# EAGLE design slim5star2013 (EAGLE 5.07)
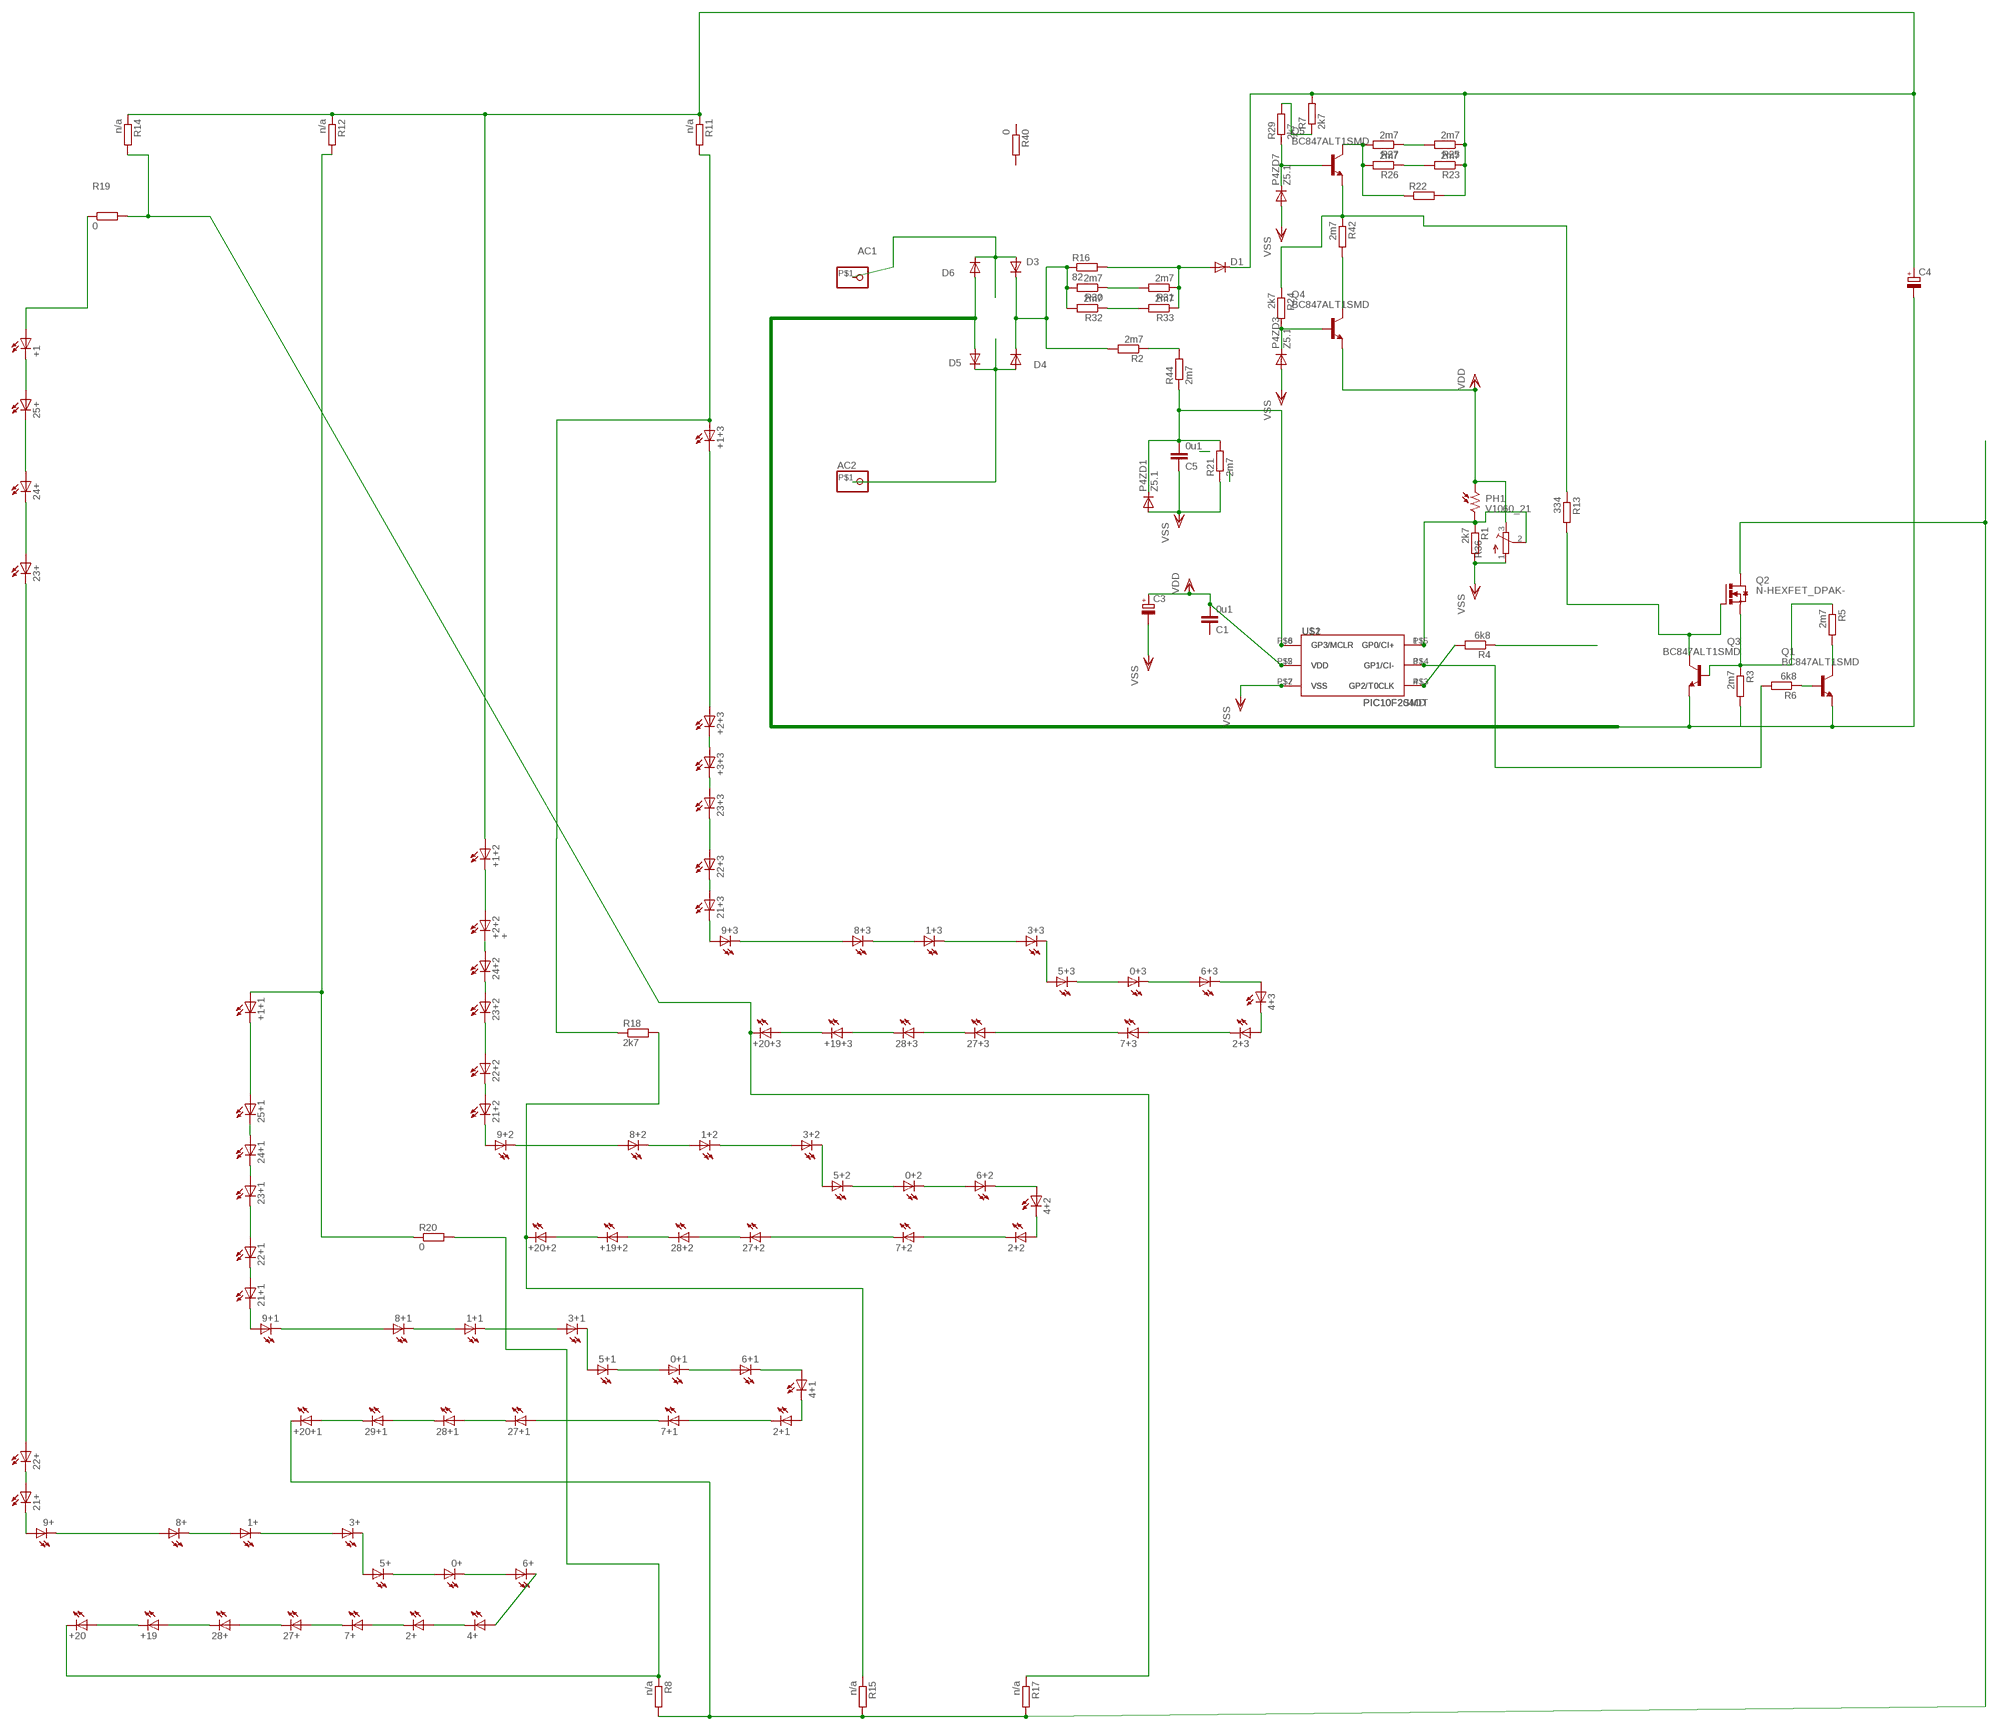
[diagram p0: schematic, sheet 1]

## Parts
0+  LED1210  [1210]
0+1  LED1210  [1210]
0+2  LED1210  [1210]
0+3  LED1210  [1210]
1+  LED1210  [1210]
1+1  LED1210  [1210]
1+2  LED1210  [1210]
1+3  LED1210  [1210]
2+  LED1210  [1210]
2+1  LED1210  [1210]
2+2  LED1210  [1210]
2+3  LED1210  [1210]
3+  LED1210  [1210]
3+1  LED1210  [1210]
3+2  LED1210  [1210]
3+3  LED1210  [1210]
4+  LED1210  [1210]
4+1  LED1210  [1210]
4+2  LED1210  [1210]
4+3  LED1210  [1210]
5+  LED1210  [1210]
5+1  LED1210  [1210]
5+2  LED1210  [1210]
5+3  LED1210  [1210]
6+  LED1210  [1210]
6+1  LED1210  [1210]
6+2  LED1210  [1210]
6+3  LED1210  [1210]
7+  LED1210  [1210]
7+1  LED1210  [1210]
7+2  LED1210  [1210]
7+3  LED1210  [1210]
8+  LED1210  [1210]
8+1  LED1210  [1210]
8+2  LED1210  [1210]
8+3  LED1210  [1210]
9+  LED1210  [1210]
9+1  LED1210  [1210]
9+2  LED1210  [1210]
9+3  LED1210  [1210]
21+  LED1210  [1210]
21+1  LED1210  [1210]
21+2  LED1210  [1210]
21+3  LED1210  [1210]
22+  LED1210  [1210]
22+1  LED1210  [1210]
22+2  LED1210  [1210]
22+3  LED1210  [1210]
23+  LED1210  [1210]
23+1  LED1210  [1210]
23+2  LED1210  [1210]
23+3  LED1210  [1210]
24+  LED1210  [1210]
24+1  LED1210  [1210]
24+2  LED1210  [1210]
25+  LED1210  [1210]
25+1  LED1210  [1210]
27+  LED1210  [1210]
27+1  LED1210  [1210]
27+2  LED1210  [1210]
27+3  LED1210  [1210]
28+  LED1210  [1210]
28+1  LED1210  [1210]
28+2  LED1210  [1210]
28+3  LED1210  [1210]
29+1  LED1210  [1210]
+1  LED1210  [1210]
+1+1  LED1210  [1210]
+1+2  LED1210  [1210]
+1+3  LED1210  [1210]
+2+2  +  LED1210  [1210]
+2+3  LED1210  [1210]
+3+3  LED1210  [1210]
+19  LED1210  [1210]
+19+2  LED1210  [1210]
+19+3  LED1210  [1210]
+20  LED1210  [1210]
+20+1  LED1210  [1210]
+20+2  LED1210  [1210]
+20+3  LED1210  [1210]
AC1  PINHD-1X1SMD  [SMD1X1]
AC2  PINHD-1X1SMD  [SMD1X1]
C1  0u1  C-EUC1206  [C1206]
C3  CPOL-EUE  [PANASONIC_E]
C4  CPOL-EUSANYO_SMD_F12  [SANYO-OSCON_SMD_F12]
C5  0u1  C-EUC1206  [C1206]
D1  DIODE-MINIMELF  [MINIMELF]
D3  DIODE-SOD80C  [SOD80C]
D4  DIODE-SOD80C  [SOD80C]
D5  DIODE-SOD80C  [SOD80C]
D6  DIODE-SOD80C  [SOD80C]
P4ZD1  Z5.1  DIODE-MINIMELF  [MINIMELF]
P4ZD3  Z5.1  DIODE-MINIMELF  [MINIMELF]
P4ZD7  Z5.1  DIODE-MINIMELF  [MINIMELF]
PH1  V1060_21  [TO-5_V10]
Q1  BC847ALT1SMD  [SOT23]
Q2  N-HEXFET_DPAK-  [TO252]
Q3  BC847ALT1SMD  [SOT23]
Q4  BC847ALT1SMD  [SOT23]
Q5  BC847ALT1SMD  [SOT23]
R1  2k7  R-EU_R1206  [R1206]
R2  2m7  R-EU_R2010  [R2010]
R3  2m7  R-EU_R1210  [R1210]
R4  6k8  R-EU_R1206  [R1206]
R5  2m7  R-EU_R1210  [R1210]
R6  6k8  R-EU_R1206  [R1206]
R7  2k7  R-EU_R1206  [R1206]
R8  n/a  R-EU_R0402  [R0402]
R11  n/a  R-EU_R0402  [R0402]
R12  n/a  R-EU_R0402  [R0402]
R13  334  R-EU_R1206  [R1206]
R14  n/a  R-EU_R0402  [R0402]
R15  n/a  R-EU_R0402  [R0402]
R16  82  R-EU_SMD15  [SMDCARB15]
R17  n/a  R-EU_R0402  [R0402]
R18  2k7  R-EU_R0402  [R0402]
R19  0  R-EU_R0402  [R0402]
R20  0  R-EU_R0402  [R0402]
R21  2m7  R-EU_R1206  [R1206]
R22  R-EU_SMD15  [SMDCARB15]
R23  2m7  R-EU_R1210  [R1210]
R24  2k7  R-EU_R1206  [R1206]
R25  2m7  R-EU_R1210  [R1210]
R26  2m7  R-EU_R1210  [R1210]
R27  2m7  R-EU_R1210  [R1210]
R29  2k7  R-EU_R1206  [R1206]
R30  2m7  R-EU_R1210  [R1210]
R31  2m7  R-EU_R1210  [R1210]
R32  2m7  R-EU_R1210  [R1210]
R33  2m7  R-EU_R1210  [R1210]
R36  TRIM_EU-SM-42/43A  [SM-42/43A]
R40  0  R-EU_R2010  [R2010]
R42  2m7  R-EU_R2010  [R2010]
R44  2m7  R-EU_R2010  [R2010]
U$1  PIC10F2SMD  [DIL8SMD]
U$2  PIC10F204OT  [SOT23-6]

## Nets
AC1: Q5.2(E) R13.1 R24.1 R42.1
AC2: AC2.P$1 D4.A D5.C
BATT-: C4.- D5.A D6.A Q1.2(E) Q3.2(E) R3.2
D+: +1+2.P$1(A) C4.+ D1.C R7.2 R11.1 R12.1 R14.1 R22.P$2 R23.1 R25.1
MINUS: +20+1.P$2(C) Q2.3(D) R8.2 R15.2 R17.2
N$1: +1+3.P$1(A) R11.2 R18.1
N$2: +1+1.P$1(A) R12.2 R20.1
N$4: +1.P$1(A) R19.1
N$5: Q4.3(C) R42.2
N$6: 8+.P$1(A) 9+.P$2(C)
N$7: +19.P$2(C) +20.P$1(A)
N$8: 28+.P$2(C) +19.P$1(A)
N$9: 27+.P$2(C) 28+.P$1(A)
N$10: 29+1.P$2(C) +20+1.P$1(A)
N$11: 28+1.P$2(C) 29+1.P$1(A)
N$12: 2+.P$2(C) 7+.P$1(A)
N$13: 7+.P$2(C) 27+.P$1(A)
N$14: 2+.P$1(A) 4+.P$2(C)
N$15: 4+.P$1(A) 6+.P$2(C)
N$16: 0+.P$2(C) 6+.P$1(A)
N$17: 0+.P$1(A) 5+.P$2(C)
N$18: 3+.P$2(C) 5+.P$1(A)
N$19: 1+.P$2(C) 3+.P$1(A)
N$20: 1+.P$1(A) 8+.P$2(C)
N$21: 27+1.P$2(C) 28+1.P$1(A)
N$22: 2+1.P$1(A) 4+1.P$2(C)
N$23: 9+.P$1(A) 21+.P$2(C)
N$24: 21+.P$1(A) 22+.P$2(C)
N$25: 22+.P$1(A) 23+.P$2(C)
N$26: 24+.P$1(A) 25+.P$2(C)
N$27: 25+.P$1(A) +1.P$2(C)
N$28: 23+.P$1(A) 24+.P$2(C)
N$29: 4+1.P$1(A) 6+1.P$2(C)
N$30: 0+1.P$2(C) 6+1.P$1(A)
N$31: 0+1.P$1(A) 5+1.P$2(C)
N$32: 3+1.P$2(C) 5+1.P$1(A)
N$33: 1+1.P$2(C) 3+1.P$1(A)
N$34: 1+1.P$1(A) 8+1.P$2(C)
N$35: 9+1.P$1(A) 21+1.P$2(C)
N$36: 21+1.P$1(A) 22+1.P$2(C)
N$37: 22+1.P$1(A) 23+1.P$2(C)
N$38: 25+1.P$1(A) +1+1.P$2(C)
N$39: 24+1.P$1(A) 25+1.P$2(C)
N$40: 23+1.P$1(A) 24+1.P$2(C)
N$41: 2+1.P$2(C) 7+1.P$1(A)
N$42: 7+1.P$2(C) 27+1.P$1(A)
N$43: 8+1.P$1(A) 9+1.P$2(C)
N$45: +20+3.P$2(C) R14.2 R17.1 R19.2
N$46: +19+2.P$2(C) +20+2.P$1(A)
N$47: 28+2.P$2(C) +19+2.P$1(A)
N$48: 27+2.P$2(C) 28+2.P$1(A)
N$49: 2+2.P$1(A) 4+2.P$2(C)
N$50: 4+2.P$1(A) 6+2.P$2(C)
N$51: 0+2.P$2(C) 6+2.P$1(A)
N$52: 0+2.P$1(A) 5+2.P$2(C)
N$53: 3+2.P$2(C) 5+2.P$1(A)
N$54: 1+2.P$2(C) 3+2.P$1(A)
N$55: 1+2.P$1(A) 8+2.P$2(C)
N$56: 9+2.P$1(A) 21+2.P$2(C)
N$57: 21+2.P$1(A) 22+2.P$2(C)
N$58: 22+2.P$1(A) 23+2.P$2(C)
N$59: +1+2.P$2(C) +2+2.P$1(A)
N$60: 24+2.P$1(A) +2+2.P$2(C)
N$61: 23+2.P$1(A) 24+2.P$2(C)
N$62: 2+2.P$2(C) 7+2.P$1(A)
N$63: 7+2.P$2(C) 27+2.P$1(A)
N$64: 8+2.P$1(A) 9+2.P$2(C)
N$65: +20+2.P$2(C) R15.1 R18.2
N$66: +20.P$2(C) R8.1 R20.2
N$67: +19+3.P$2(C) +20+3.P$1(A)
N$68: 28+3.P$2(C) +19+3.P$1(A)
N$69: 27+3.P$2(C) 28+3.P$1(A)
N$70: 2+3.P$1(A) 4+3.P$2(C)
N$71: 4+3.P$1(A) 6+3.P$2(C)
N$72: 0+3.P$2(C) 6+3.P$1(A)
N$73: 0+3.P$1(A) 5+3.P$2(C)
N$74: 3+3.P$2(C) 5+3.P$1(A)
N$75: 1+3.P$2(C) 3+3.P$1(A)
N$76: 1+3.P$1(A) 8+3.P$2(C)
N$77: 9+3.P$1(A) 21+3.P$2(C)
N$78: 21+3.P$1(A) 22+3.P$2(C)
N$79: 22+3.P$1(A) 23+3.P$2(C)
N$80: +1+3.P$2(C) +2+3.P$1(A)
N$81: +2+3.P$2(C) +3+3.P$1(A)
N$82: 23+3.P$1(A) +3+3.P$2(C)
N$83: 2+3.P$2(C) 7+3.P$1(A)
N$84: 7+3.P$2(C) 27+3.P$1(A)
N$85: 8+3.P$1(A) 9+3.P$2(C)
N$86: D1.A R16.P$2 R31.1 R33.1
N$88: PH1.2 R1.1 R36.2(S) U$1.P$5(GP0/CI+) U$2.1(GP0/CI+)
N$91: D3.C D4.C R2.2 R16.P$1 R30.2 R32.2
N$92: Q5.3(C) R22.P$1 R26.2 R27.2
N$93: AC1.P$1 D3.A D6.C
N$94: Q2.1(G) Q3.3(C) R13.2
N$95: R4.2 U$1.P$3(GP2/T0CLK) U$2.4(GP2/T0CLK)
N$96: C5.2 P4ZD1.C R21.2 R44.1 U$1.P$8(GP3/MCLR) U$2.6(GP3/MCLR)
N$97: R2.1 R44.2
N$98: Q1.1(B) R6.1
N$99: R23.2 R26.1
N$100: R25.2 R27.1
N$101: Q1.3(C) R5.2
N$102: R6.2 U$1.P$4(GP1/CI-) U$2.3(GP1/CI-)
N$103: P4ZD3.C Q4.1(B) R24.2
N$104: P4ZD7.C Q5.1(B) R29.1
N$105: Q2.2(S) Q3.1(B) R3.1 R5.1
N$106: R7.1 R29.2
N$107: R30.1 R31.2
N$108: R32.1 R33.2
PIR: R4.1
VDD: C1.2 C3.+ PH1.1 Q4.2(E) R36.3(E) U$1.P$2(VDD) U$2.5(VDD)
VSS: C3.- C5.1 P4ZD1.A P4ZD3.A P4ZD7.A R1.2 R21.1 R36.1(A) U$1.P$7(VSS) U$2.2(VSS)
Unconnected: C1.1 R40.1 R40.2

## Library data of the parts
0+ 0+1-0+3 1+ 1+1-1+3 2+ 2+1-2+3 3+ 3+1-3+3 4+ 4+1-4+3 5+ 5+1-5+3 6+ 6+1-6+3 7+ 7+1-7+3 8+ 8+1-8+3 9+ 9+1-9+3 21+ 21+1-21+3 22+ 22+1-22+3 23+ 23+1-23+3 24+ 24+1 24+2 25+ 25+1 27+ 27+1-27+3 28+ 28+1-28+3 29+1 +1 +1+1-+1+3 +2+2 +2+3 +3+3 +19 +19+2 +19+3 +20 +20+1-+20+3 = led(2):LED: LED
AC1 AC2 = pinhead:PINHD-1X1: PIN HEADER
C1 C5 = rcl:C-EU: CAPACITOR, European symbol
C3 C4 = rcl-2:CPOL-EU: POLARIZED CAPACITOR, European symbol
D1 D3-D6 P4ZD1 P4ZD3 P4ZD7 = diode:DIODE-: DIODE
PH1 = photo-elements:?1060*: Sensor Street Light control
Q1 Q3-Q5 = transistor-npn:BC847*: NPN Transistor
Q2 = transistor-power:N-HEXFET_?-*: HEXFET® Power MOSFET
R1-R8 R11-R15 R17-R21 R23-R27 R29-R33 R40 R42 R44 = rcl-2:R-EU_: RESISTOR, European symbol
R16 R22 = rcl:R-EU_: RESISTOR, European symbol
R36 = pot:TRIM_EU-: POTENTIOMETER
U$1 U$2 = microchip-5:PIC10F2*: uPC nW 0,25/0,5k Program Flash memory Comparator

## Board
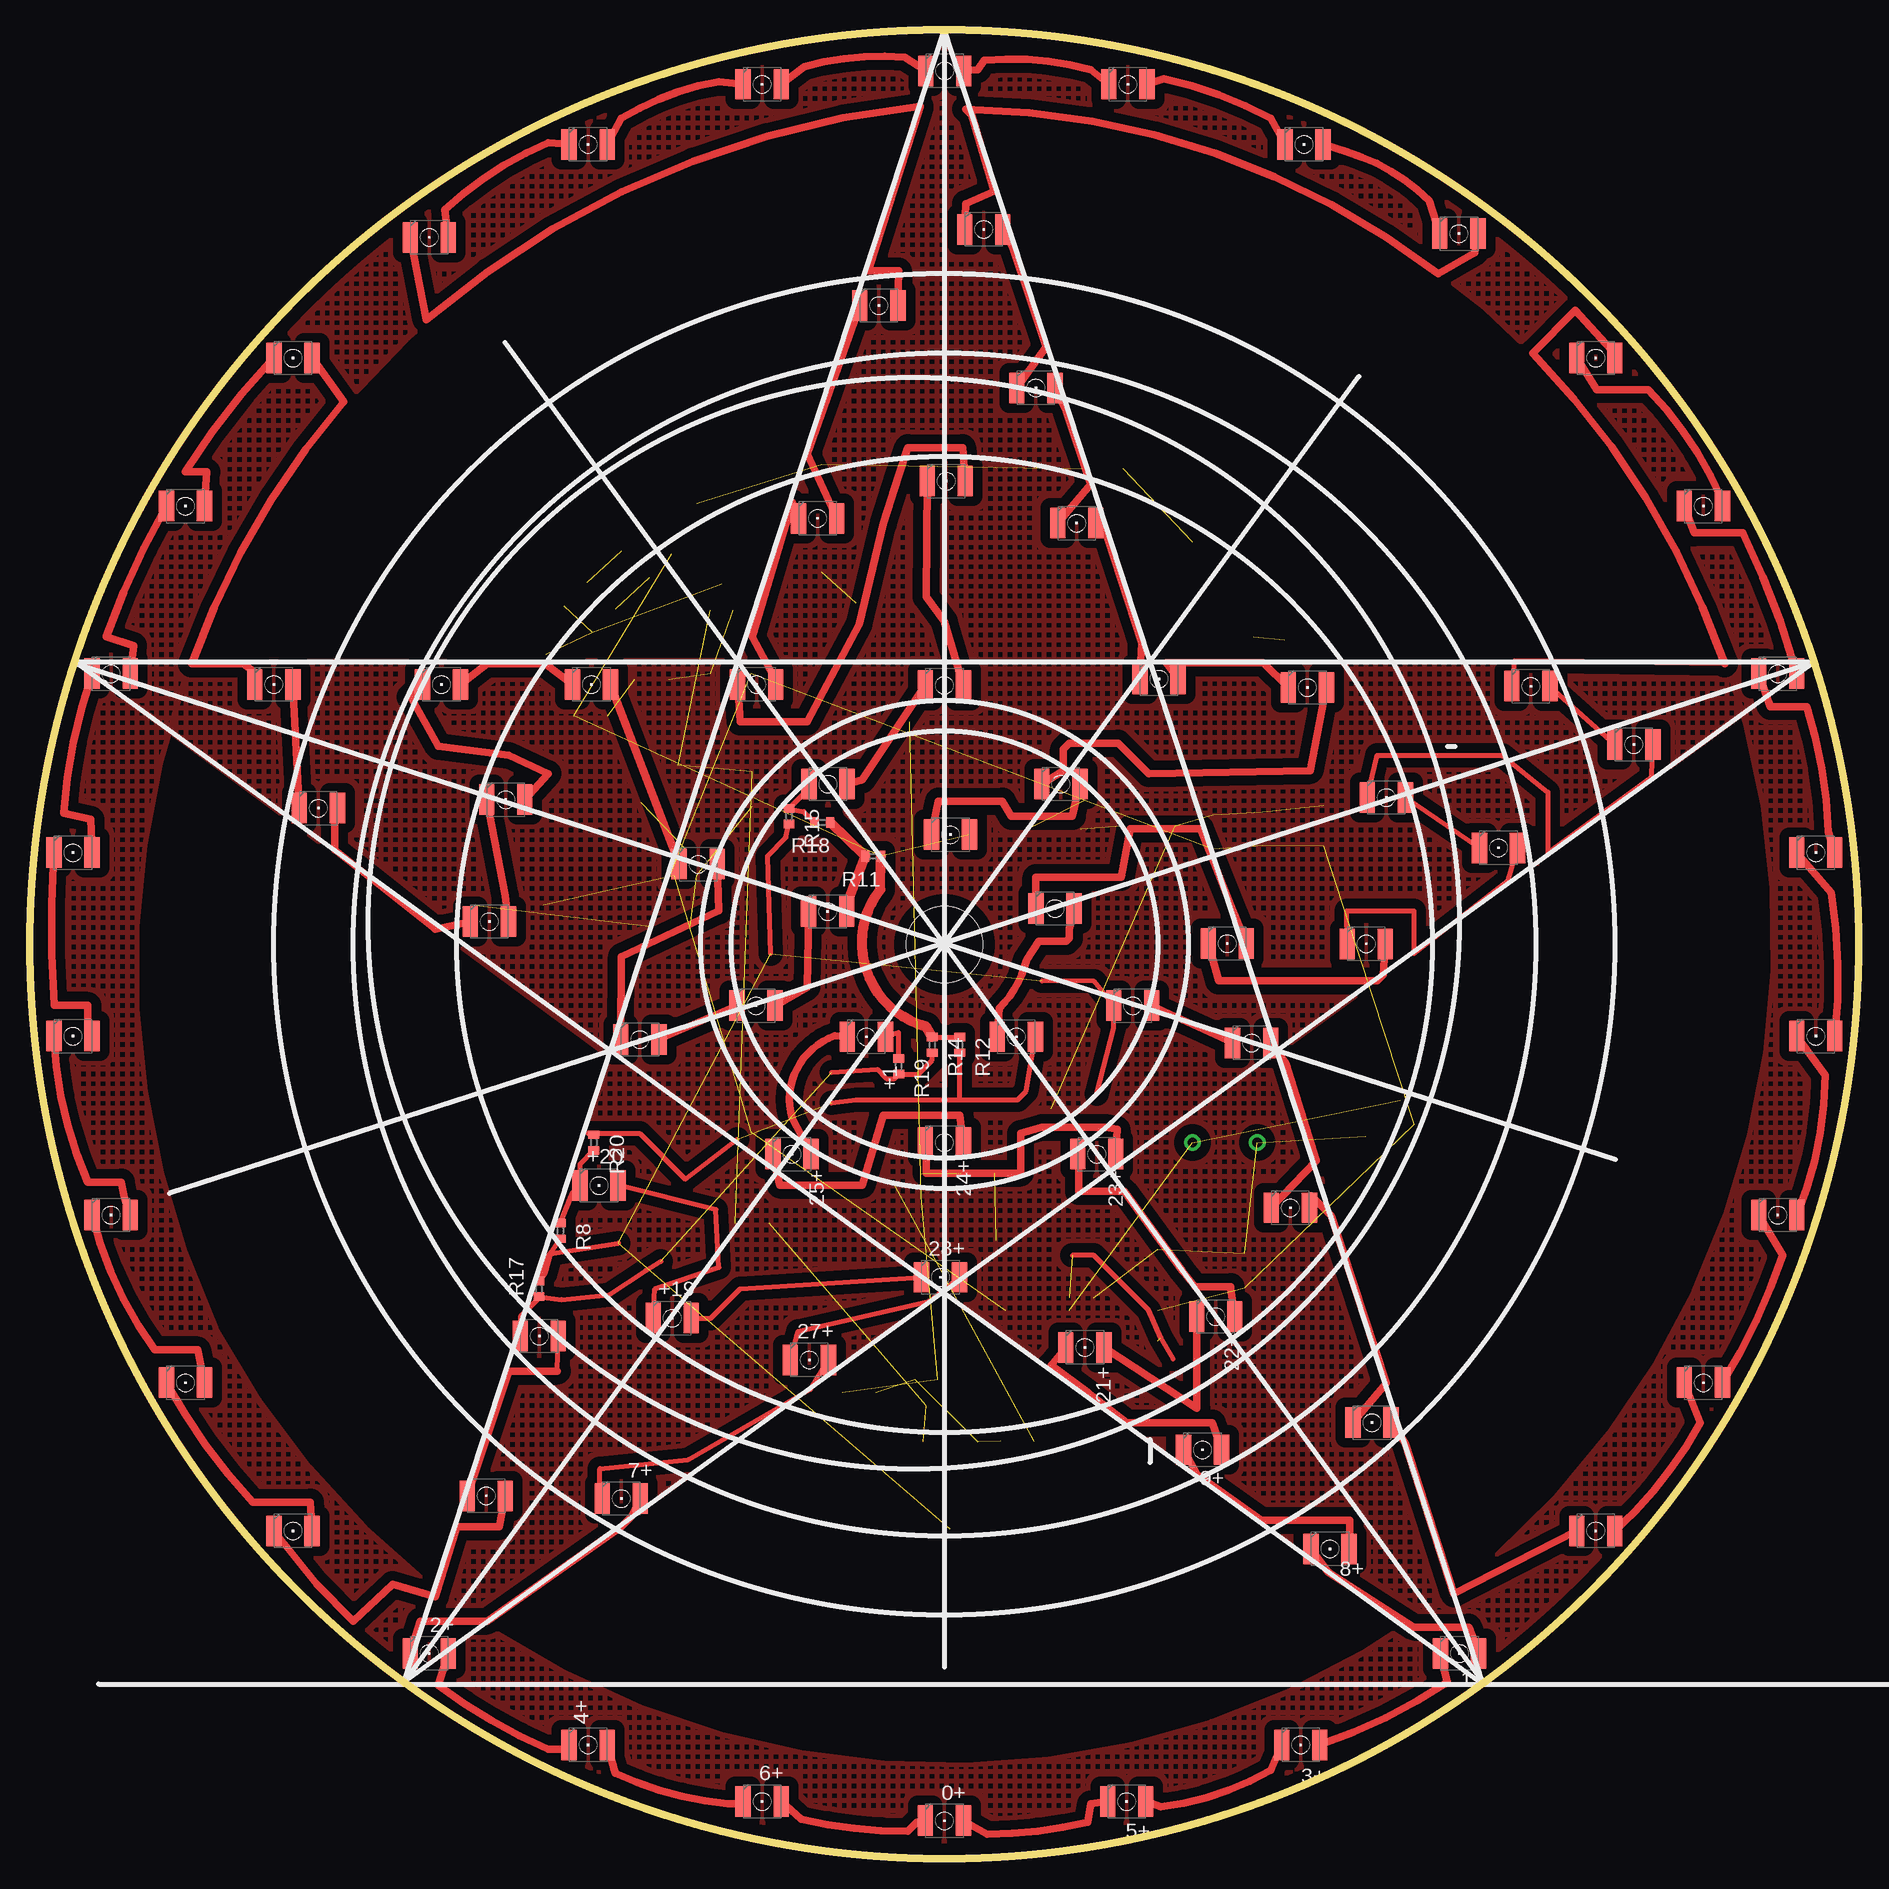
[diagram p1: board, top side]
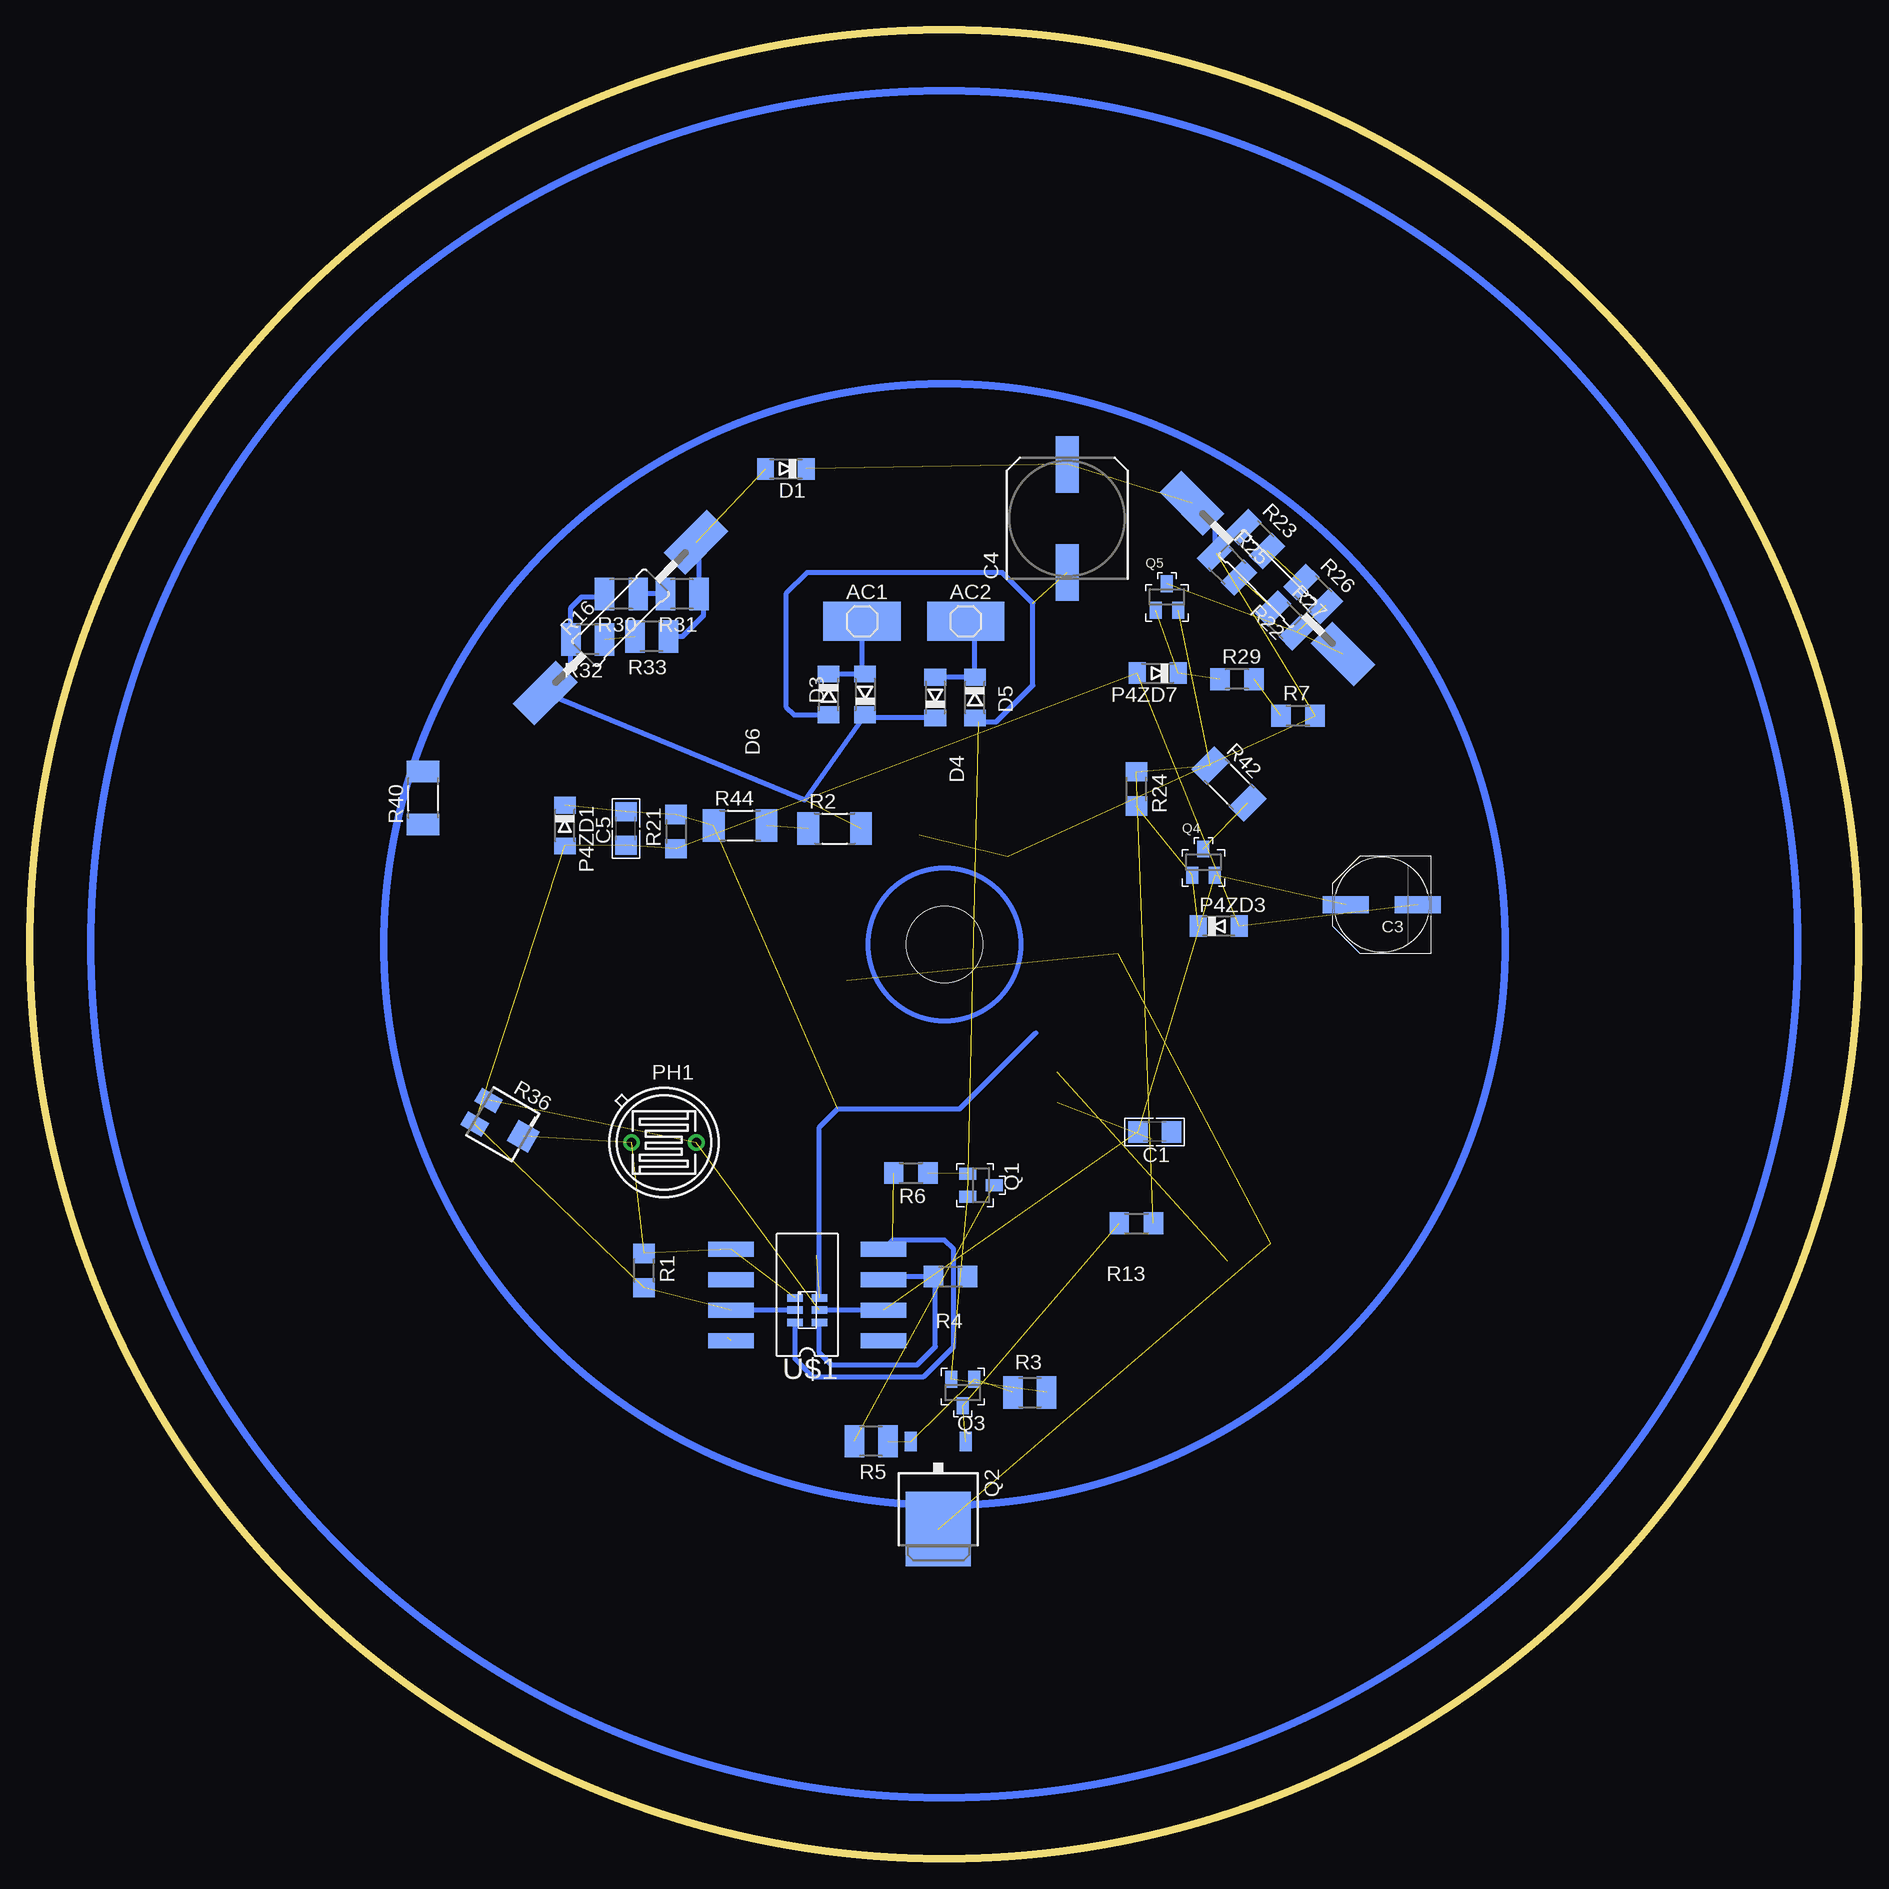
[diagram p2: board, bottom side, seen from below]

Size 152.4 x 152.4 mm. Coordinates in mm from the lower left corner, seen from the top.
Outline: circle at 76.2,76.2 radius 76.2
Copper layers (1*16): Top 0.035mm / dielectric 1.5mm / Bottom 0.035mm
Design rules "default": minimum track width 10mil, minimum drill 24mil, track to track 8mil, track to pad 8mil, pad to pad 8mil, via to via 8mil, smd to smd 8mil, copper to edge 40mil, drill to drill 8mil, minimum pad ring 10mil, minimum via ring 8mil, stop-mask expansion 4mil, vias tented up to drill 0mil, thermal gap 10mil
Holes 6.35 mm at 76.2,76.2

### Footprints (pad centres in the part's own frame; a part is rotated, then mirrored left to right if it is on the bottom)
1210 = smd 1.27 x 2.54: P$1 1.587,0; P$2 -1.587,0
SMD1X1 = smd 6.452 x 3.251: P$1 0,0
C1206 = smd 1.6 x 1.8: 1 -1.4,0; 2 1.4,0
PANASONIC_E = smd 3.8 x 1.4: + 3,0; - -3,0
SANYO-OSCON_SMD_F12 = smd 4.7 x 1.9: + 4.5,0; - -4.5,0
MINIMELF = smd 1.4 x 1.8: A 1.7,0; C -1.7,0
SOD80C = smd 1.4 x 1.8: A 1.7,0; C -1.7,0
TO-5_V10 = drill 0.8 pad 1.4 round: 1 -2.7,0; 2 2.7,0
SOT23 = smd 1 x 1.4: 1 -0.95,-1.1; 2 0.95,-1.1; 3 0,1.1
TO252 = smd 1 x 1.6: 1 -2.28,-3.53; 2 2.28,-3.53 | smd 5.4 x 6.2: 3 0,3.77
R1206 = smd 1.6 x 1.803: 1 -1.422,0; 2 1.422,0
R2010 = smd 1.8 x 2.7: 1 -2.2,0; 2 2.2,0
R1210 = smd 1.6 x 2.7: 1 -1.4,0; 2 1.4,0
R0402 = smd 0.7 x 0.9: 1 -0.65,0; 2 0.65,0
SMDCARB15 = smd 5.08 x 2.54: P$1 -8.89,0; P$2 8.89,0
SM-42/43A = smd 2 x 1.3: 1 2,1.15; 3 2,-1.15 | smd 2 x 2: 2 -2,0
DIL8SMD = smd 1.27 x 3.81: P$1 -3.81,-6.35; P$2 -1.27,-6.35; P$3 1.27,-6.35; P$4 3.81,-6.35; P$5 3.81,6.35; P$6 1.27,6.35; P$7 -1.27,6.35; P$8 -3.81,6.35
SOT23-6 = smd 0.635 x 1.27: 1 -1.016,-1.016; 2 0,-1.016; 3 1.016,-1.016; 4 1.016,1.016; 5 0,1.016; 6 -1.016,1.016

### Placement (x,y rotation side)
0+  76.2,3.17 0 top
0+1  148.82,83.85 0 top
0+2  61.01,147.88 0 top
0+3  12.95,112.73 0 top
1+  119.13,17.12 0 top
1+1  130.48,125.07 0 top
1+2  106.17,142.88 0 top
1+3  24.03,87.55 0 top
2+  33.27,17.12 0 top
2+1  139.45,39.67 0 top
2+2  70.74,129.44 0 top
2+3  3.58,68.55 0 top
3+  105.89,9.5 0 top
3+1  139.45,112.73 0 top
3+2  91.49,147.88 0 top
3+3  20.32,97.87 0 top
4+  46.51,9.5 0 top
4+1  145.64,53.64 0 top
4+2  33.27,135.13 0 top
4+3  3.58,83.85 0 top
5+  91.39,4.78 0 top
5+1  145.64,98.76 0 top
5+2  76.23,149 0 top
5+3  21.92,125.07 0 top
6+  61.01,4.78 0 top
6+1  148.82,68.55 0 top
6+2  46.51,142.88 0 top
6+3  6.76,98.76 0 top
7+  49.28,30.02 0 top
7+1  130.48,27.33 0 top
7+2  65.63,111.71 0 top
7+3  6.76,53.64 0 top
8+  108.33,25.83 0 top
8+1  125.07,97.71 0 top
8+2  119.08,135.43 0 top
8+3  38.28,78.11 0 top
9+  97.71,34.09 0 top
9+1  133.65,92.86 0 top
9+2  79.48,135.79 0 top
9+3  39.65,88.27 0 top
21+  87.91,42.62 0 top
21+1  113.03,88.44 0 top
21+2  83.82,122.58 0 top
21+3  34.29,97.87 0 top
22+  98.81,45.19 0 top
22+1  122.38,84.25 0 top
22+2  87.22,111.3 0 top
22+3  46.79,97.87 0 top
23+  88.9,58.72 0 top
23+1  111.35,76.25 0 top
23+2  94.08,98.32 0 top
23+3  55.68,82.88 0 top
24+  76.2,59.69 0 top
24+1  99.77,76.28 0 top
24+2  106.45,97.61 0 top
25+  63.5,58.72 0 top
25+1  85.42,79.2 0 top
27+  64.95,41.58 0 top
27+1  111.84,36.35 0 top
27+2  60.55,97.87 0 top
27+3  12.95,39.67 0 top
28+  75.87,48.46 0 top
28+1  105.03,54.25 0 top
28+2  76.35,114.81 0 top
28+3  21.92,27.33 0 top
29+1  101.8,68 0 top
+1  69.7,68.5 0 top
+1+1  82.19,68.5 0 top
+1+2  76.71,85.34 0 top
+1+3  66.47,78.94 0 top
+2+2  85.9,89.56 0 top
+2+3  60.5,71.09 0 top
+3+3  50.83,68.28 0 top
+19  53.52,45.06 0 top
+19+2  76.2,97.79 0 top
+19+3  38.02,30.25 0 top
+20  47.42,56.11 0 top
+20+1  91.9,71.09 0 top
+20+2  66.5,89.56 0 top
+20+3  42.44,43.56 0 top
AC1  83.06,103.12 0 bottom
AC2  74.42,103.12 0 bottom
C1  58.67,60.58 180 bottom
C3  39.75,79.5 180 bottom
C4  65.97,111.7 90 bottom
C5  102.74,85.85 90 bottom
D1  89.41,115.82 180 bottom
D3  82.8,97.03 90 bottom
D4  76.96,96.77 90 bottom
D5  73.66,96.77 270 bottom
D6  85.85,97.03 270 bottom
P4ZD1  107.82,86.11 270 bottom
P4ZD3  53.34,77.72 0 bottom
P4ZD7  58.42,98.81 180 bottom
PH1  99.57,59.69 180 bottom
Q1  73.15,56.13 270 bottom
Q2  76.71,31.24 180 bottom
Q3  74.68,38.86 180 bottom
Q4  54.61,83.06 0 bottom
Q5  57.66,105.16 0 bottom
R1  101.22,49.02 270 bottom
R2  85.34,85.85 0 bottom
R3  69.09,38.86 0 bottom
R4  75.69,48.51 180 bottom
R5  82.3,34.8 180 bottom
R6  78.99,57.15 180 bottom
R7  46.74,95.25 0 bottom
R8  44.2,52.32 270 top
R11  70.26,83.55 180 top
R12  77.47,67.82 270 top
R13  60.2,52.96 180 bottom
R14  75.18,67.82 270 top
R15  63.25,86.87 270 top
R16  103.18,103.43 45 bottom
R17  42.42,47.5 90 top
R18  66.04,86.36 180 top
R19  72.39,66.04 270 top
R20  46.99,59.69 270 top
R21  98.55,85.6 90 bottom
R22  49.28,106.68 135 bottom
R23  50.29,109.98 315 bottom
R24  60.2,89.15 270 bottom
R25  52.65,107.77 315 bottom
R26  45.47,105.41 315 bottom
R27  47.83,103.2 315 bottom
R29  51.82,98.3 0 bottom
R30  103.12,105.41 180 bottom
R31  98.04,105.41 180 bottom
R32  105.92,101.6 180 bottom
R33  100.58,101.85 180 bottom
R36  113.03,61.21 150 bottom
R40  119.63,88.39 90 bottom
R42  52.47,89.56 315 bottom
R44  93.22,86.11 0 bottom
U$1  87.63,46.99 90 bottom
U$2  87.63,45.72 270 bottom

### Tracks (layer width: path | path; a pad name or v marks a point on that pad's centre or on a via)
AC1  (3 unrouted)
AC2
  Bottom 0.406: AC2.P$1 73.66,103.12 D5.C D4.A
BATT-  (4 unrouted)
  Bottom 0.406: D6.A 88.72,95.33 89.41,96.01 89.41,105.41 87.63,107.19 71.37,107.19 68.83,104.65 68.83,97.79 71.88,94.74 73.33,94.74 D5.A
D+  (5 unrouted)
  Top 0.406: R14.1 R12.1
  Top 0.813: R14.1 74.68,69.34 arc-113 70.87,80.77 R11.1
  Bottom 0.406: R23.1 53.49,108.76 R25.1 53.64,111.05 R22.P$2
MINUS  (3 unrouted)
  Top 0.406: R15.2 62.99,85.09 61.47,83.57 61.72,75.44 | 49.02,51.31 43.32,50.43 R17.2 42.93,48.77 43.43,50.55 R8.2 | 84.33,73.15 88.67,73.13 +20+1.P$2 90.31,69.23 88.9,63.75
N$1
  Top 0.813: R18.1 R11.2 68.07,79.5 +1+3.P$1
N$2  (1 unrouted)
  Top 0.406: +1+1.P$1 83.02,63.97 82.3,63.25 77.47,63.25 | 66.8,62.99 68.83,63.25 77.47,63.25 | 58.93,59.94 54.61,56.64 50.8,60.45 46.88,60.45 | 46.88,60.45 46.48,60.45 | R20.1 46.88,60.45 | 77.47,63.25 R12.2
N$3
  pour Top (isolate 0.813, hatched): 48.31,66.78 31.24,14.66 76.33,47.45 120.95,14.66 104.27,67.36 148.74,99.77 93.29,99.72 76.2,152.4 59.18,99.87 3.76,99.75
N$4
  Top 0.406: R19.1 72.39,68.85 +1.P$1
N$5  (1 unrouted)
N$6
  Top 0.61: 8+.P$1 109.98,28.19 102.62,28.19 97.28,32 9+.P$2
N$7
  Top 0.406: +19.P$2 52.07,47.5 57.4,49.28 57.15,54.1 +20.P$1
N$8
  Top 0.406: +19.P$1 56.74,45.06 59.18,47.5 28+.P$2
N$9
  Top 0.406: 28+.P$1 74.93,46.48 64.01,43.94 27+.P$2
N$10
  Top 0.61: +20+1.P$1 29+1.P$2
N$11
  Top 0.61: 28+1.P$2 107.19,58.17 104.65,66.29 29+1.P$1
N$12
  Top 0.61: 7+.P$1 50.1,28.51 49.28,27.69 38.1,19.81 32.51,19.81 2+.P$2
N$13
  Top 0.406: 27+.P$1 65.02,39.12 54.86,33.27 47.5,32.51 47.5,30.99 47.75,30.99 48.01,30.48 7+.P$2
N$14
  Top 0.61: 2+.P$1 34.04,14.48 arc14 43.18,9.14 44.92,9.14 4+.P$2
N$15
  Top 0.61: 4+.P$1 48.77,7.11 arc19 58.17,4.57 59.22,4.57 6+.P$2
N$16
  Top 0.61: 6+.P$1 64.26,3.3 arc13 73.15,2.29 73.91,3.05 0+.P$2
N$17
  Top 0.61: 0+.P$1 79.76,2.03 arc13 88.14,3.05 88.39,4.57 5+.P$2
N$18
  Top 0.61: 5+.P$1 94.23,4.32 arc23 103.38,7.37 3+.P$2
N$19
  Top 0.61: 3+.P$1 arc16 118.11,14.73 1+.P$2
N$20
  Top 0.61: 1+.P$1 119.89,19.3 115.32,19.3 108.2,23.88 8+.P$2
N$21
  Top 0.61: 27+1.P$2 113.03,39.62 108.46,53.59 106.78,55.27 28+1.P$1
N$22
  Top 0.61: 4+1.P$2 146.05,50.29 arc-13 2+1.P$1
N$23
  Top 0.61: 9+.P$1 98.54,36.34 91.4,36.34 88.1,38.88 88.14,38.86 85.09,41.15 21+.P$2
N$24
  Top 0.61: 21+.P$1 97.24,37.54 22+.P$2
N$25
  Top 0.61: 22+.P$1 100.08,47.5 100.08,47.69 97.09,47.69 96.01,49.02 91.19,55.63 87.38,55.63 87.38,58.81 23+.P$2
N$26
  Top 0.61: 25+.P$2 62.48,56.13 69.34,56.13 71.12,61.98 77.47,61.98 24+.P$1
N$27
  Top 0.61: +1.P$2 67.06,68.58 arc86 63.5,61.72 25+.P$1
N$28
  Top 0.61: 23+.P$1 90.59,60.8 89.66,60.96 84.33,60.96 82.55,60.45 82.55,57.15 74.68,57.15 74.68,58.74 24+.P$2
N$29
  Top 0.61: 6+1.P$2 149.61,65.28 arc-22 4+1.P$1
N$30
  Top 0.61: 0+1.P$2 150.11,80.52 arc-15 6+1.P$1
N$31
  Top 0.61: 5+1.P$2 145.03,96.01 148.08,96.01 arc-15 149.86,85.6 0+1.P$1
N$32
  Top 0.61: 3+1.P$2 138.68,110.49 142.75,110.49 arc-10 147.07,99.31 5+1.P$1
N$33
  Top 0.61: 1+1.P$2 130.56,122.43 134.87,122.43 arc-21 140.97,113.28 3+1.P$1
N$34
  Top 0.406: 8+1.P$2 123.7,99.82 141.22,99.57
  Top 0.61: 141.22,99.57 arc25 125.22,125.48 128.78,129.03 131.32,126.24 131.83,125.73 1+1.P$1
N$35
  Top 0.406: 9+1.P$1 135.13,90.17 126.49,83.82 126.49,88.9 122.68,91.95 112.27,91.95 21+1.P$2
N$36
  Top 0.406: 21+1.P$1 22+1.P$2
N$37
  Top 0.406: 22+1.P$1 123.19,81.53 115.32,75.44 115.32,78.99 109.73,78.99 23+1.P$2
N$38
  Top 0.61: +1+1.P$2 80.77,70.87 arc31 83.06,74.93 84.07,76.45 86.36,76.45 86.61,76.71 86.61,77.47 25+1.P$1
N$39
  Top 0.61: 25+1.P$2 83.82,81.79 90.93,81.79 91.69,85.85 97.54,85.85 24+1.P$1
N$40
  Top 0.61: 24+1.P$2 99.06,73.15 112.27,73.15 112.78,73.66 23+1.P$1
N$41
  Top 0.61: 2+1.P$2 139.19,36.32 arc-19 7+1.P$1
N$42
  Top 0.61: 7+1.P$2 118.65,22.07 114.61,34.64 27+1.P$1
N$43
  Top 0.406: 8+1.P$1 9+1.P$2
N$44
  pour Top (isolate 0.813, hatched): 76.73,152.45 arc-78 150.27,90.47 arc-83 103.84,5.31 arc-84 9.42,40.97 arc-114 75.54,152.35 74.55,145.8 arc110 15.49,44.2 arc241 76.73,145.82
N$45  (1 unrouted)
  Top 0.406: +20+3.P$2 40.89,43.6 40.89,45.21 42.53,46.85 R17.1 44.31,46.59 48.26,46.99 51.31,49.02 52.58,49.78 | 66.8,65.53 70.61,65.79 71.37,65.02 72.02,65.02 R19.2 74.03,65.39 75.18,66.55 R14.2
N$46
  Top 0.61: +19+2.P$2 69.34,89.92 +20+2.P$1
N$47
  Top 0.61: +19+2.P$1 76.2,103.12 74.68,105.16 28+2.P$2
N$48
  Top 0.61: 27+2.P$2 59.18,94.74 64.77,94.74 69.09,102.87 71.12,111.25 72.39,115.32 73.15,117.6 77.72,117.6 28+2.P$1
N$49
  Top 0.61: 4+2.P$2 33.02,128.27 arc-34 74.17,146.07 69.85,132.33 72.39,132.33 2+2.P$1
N$50
  Top 0.61: 4+2.P$1 34.54,137.41 arc-20 43.18,143 6+2.P$2
N$51
  Top 0.61: 6+2.P$1 49.28,145.03 arc-23 57.4,148.08 0+2.P$2
N$52
  Top 0.61: 0+2.P$1 64.52,149.35 arc-20 72.9,150.11 5+2.P$2
N$53
  Top 0.61: 5+2.P$1 78.99,149.1 79.5,149.86 arc-21 88.39,149.1 3+2.P$2
N$54
  Top 0.61: 3+2.P$1 94.49,148.34 arc-17 103.38,145.03 1+2.P$2
N$55
  Top 0.61: 1+2.P$1 109.73,142.24 arc-29 116.59,138.18 8+2.P$2
N$56
  Top 0.61: 21+2.P$2 84.69,125.99 81.92,134.17 9+2.P$1
N$57
  Top 0.61: 22+2.P$2 88.39,114.55 86.36,120.65 21+2.P$1
N$58
  Top 0.61: 23+2.P$2 92.65,101.33 89.82,110.06 22+2.P$1
N$59
  Top 0.61: +1+2.P$2 75.69,88.14 81.03,88.14 81.79,86.87 86.87,86.87 +2+2.P$1
N$60
  Top 0.61: +2+2.P$2 86.11,90.68 86.11,92.46 86.61,92.96 90.68,92.96 93.22,90.42 106.68,90.68 24+2.P$1
N$61
  Top 0.61: 23+2.P$1 94.68,99.67 102.75,99.67 24+2.P$2
N$62
  Top 0.61: 2+2.P$2 64.77,117.09 7+2.P$1
N$63
  Top 0.61: 7+2.P$2 63.5,113.03 60.2,101.85 62.23,98.04 27+2.P$1
N$64
  Top 0.61: 9+2.P$2 77.98,137.92 80.37,138.97 78.49,145.29 77.98,145.8 arc-37 117.35,132.08 120.4,133.86 8+2.P$1
N$65
  Top 0.406: +20+2.P$2 64.91,89.18 R15.1 64.49,87.26 R18.2
N$66
  Top 0.406: R8.1 45.21,55.49 +20.P$2 45.83,57.88 R20.2
N$67
  Top 0.406: 43.94,40.64 +20+3.P$1
  Top 0.61: +19+3.P$2 39.88,40.64 43.94,40.64
N$68
  Top 0.61: 28+3.P$2 23.88,22.86 26.92,19.81 30.23,22.86 33.78,21.84 35.56,27.69 39.12,27.69 +19+3.P$1
N$69
  Top 0.61: 27+3.P$2 arc14 18.54,29.72 23.37,29.72 28+3.P$1
N$70
  Top 0.61: 4+3.P$2 arc9 2.03,71.12 4.83,71.12 4.83,69.85 2+3.P$1
N$71
  Top 0.61: 6+3.P$2 arc14 2.79,87.12 5.08,86.61 4+3.P$1
N$72
  Top 0.61: 0+3.P$2 arc10 6.35,101.85 8.64,101.09 6+3.P$1
N$73
  Top 0.61: 0+3.P$1 14.73,115.57 12.95,115.57 arc-12 5+3.P$2
N$74
  Top 0.61: 5+3.P$1 26.16,121.41 arc21 13.46,99.57 17.78,99.57 18.78,98.82 18.54,98.81 18.78,98.03 3+3.P$2
N$75
  Top 0.61: 1+3.P$2 3+3.P$1
N$76
  Top 0.61: 8+3.P$2 33.78,77.47 25.4,84.07 25.4,87.12 1+3.P$1
N$77
  Top 0.61: 21+3.P$2 31.69,96.84 31.75,96.77 34.04,92.71 39.88,91.95 43.18,90.42 9+3.P$1
N$78
  Top 0.61: 21+3.P$1 38.1,99.57 42.93,99.57 22+3.P$2
N$79
  Top 0.61: 23+3.P$2 22+3.P$1
N$80
  Top 0.61: +1+3.P$2 64.77,72.64 +2+3.P$1
N$81
  Top 0.61: +3+3.P$1 +2+3.P$2
N$82
  Top 0.61: +3+3.P$2 49.28,75.18 57.4,78.99 23+3.P$1
N$83
  Top 0.61: 2+3.P$2 arc22 4.83,56.39 7.62,56.39 7.87,55.12 7+3.P$1
N$84
  Top 0.61: 7+3.P$2 arc23 10.41,42.42 13.97,42.42 27+3.P$1
N$85
  Top 0.61: 9+3.P$2 39.62,80.26 8+3.P$1
N$86  (1 unrouted)
  Bottom 0.406: R33.1 98.04,101.85 96.27,103.63 96.27,105.03 R31.1 96.64,109.47 R16.P$2
N$88  (4 unrouted)
N$91  (1 unrouted)
  Bottom 0.406: R30.2 104.78,105.16 106.43,105.16 107.32,104.26 R32.2 107.32,99.29 R16.P$1 87.84,88.22 D3.C 82.55,95.07 D4.C
N$92  (3 unrouted)
  Bottom 0.406: R22.P$1 41.85,100.39 41.66,100.58
N$93
  Bottom 0.406: 82.8,98.61 D3.A 83.06,98.73 | 83.06,98.73 AC1.P$1 | 83.06,98.73 D6.C
N$94  (2 unrouted)
N$95
  Bottom 0.406: U$2.4 86.61,42.16 85.6,41.15 78.49,41.15 76.96,42.67 76.96,48.36 R4.2 81.03,48.51 U$1.P$3
N$96  (6 unrouted)
  Top 0.406: 86.87,50.29 88.65,50.29 93.22,45.72 94.23,43.43 95.25,41.66
  Bottom 0.406: U$2.6 86.61,60.96 85.09,62.48 74.93,62.48 68.58,68.83
N$97  (1 unrouted)
N$98  (1 unrouted)
N$99  (1 unrouted)
N$100  (1 unrouted)
N$101  (1 unrouted)
N$102  (1 unrouted)
  Bottom 0.406: U$2.3 88.65,41.66 87.12,40.13 77.98,40.13 75.44,42.67 75.44,50.8 76.2,51.56 80.52,51.56 U$1.P$4
N$103  (2 unrouted)
N$104  (2 unrouted)
N$105  (3 unrouted)
N$106  (1 unrouted)
N$107
  Bottom 0.406: R31.2 R30.1
N$108  (1 unrouted)
VDD  (5 unrouted)
  Bottom 0.406: U$1.P$2 U$2.5
VSS  (8 unrouted)
  Bottom 0.406: U$2.2 U$1.P$7
(copper drawn outside any net)
  shapes: Bottom circle x3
